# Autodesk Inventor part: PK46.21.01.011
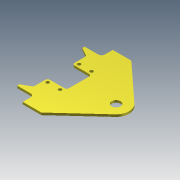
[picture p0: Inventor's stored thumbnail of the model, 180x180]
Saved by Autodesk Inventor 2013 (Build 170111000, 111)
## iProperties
Created: 2005-04
Part Number: PK46.21.01.011
Material: Steel, Mild
Document SubType Name: Modeling
Designer: salex
Manufacturer: Standard
Standards Organization: Custom
Density: 7.86 g/cm^3
Author: salex
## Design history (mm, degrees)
sketch "Эскиз1"
  geometry: L1 (77.853, 84.64)-(-265, 400); L2 (-265, 400)-(-430, 400); L3 (-430, 400)-(-430, 330); L4 (-460, 300)-(-580, 300); L5 (-500, 235)-(-500, 110); L6 (-500, 110)-(-350, 110); L7 (-330, 90)-(-330, -90); L8 (0, 0)-(-389.201, 0); L9 (77.853, -84.64)-(-265, -400); L10 (-265, -400)-(-430, -400); L11 (-500, -110)-(-350, -110); L12 (-430, -400)-(-430, -330); L13 (-460, -300)-(-580, -300); L14 (-500, -235)-(-500, -110); L15 (-580, -300)-(-580, -280); L16 (-580, -280)-(-500, -235); L17 (-580, 300)-(-580, 280); L18 (-580, 280)-(-500, 235); L19 (-500, 235)-(-500, 110); C1 r 40 at (0, 0); C2 r 15 at (-470, -140); C3 r 15 at (-360, -140); C4 r 15 at (-360, 140); C5 r 15 at (-470, 140); A1 r 115 centre (0, 0) between (77.853, -84.64) and (77.853, 84.64); A2 r 30 centre (-460, 330) between (-460, 300) and (-430, 330); A3 r 20 centre (-350, 90) between (-330, 90) and (-350, 110); A4 r 20 centre (-350, -90) between (-350, -110) and (-330, -90); A5 r 30 centre (-460, -330) between (-430, -330) and (-460, -300)
  constraints: 38 end point, 14 symmetric about line, 10 centre point, 10 point on circle, 7 perpendicular, 5 tangent, 3 equal radius, 1 coincident, 1 horizontal, 3 other
  dimensions: "d0" = 30 radius of A2; "d1" = 20 radius of A3; "d2" = 220 diameter of L6 L8; "d3" = 800 diameter of L2 L8; "d5" = 80 diameter of C1; "d6" = 330 distance from line of L7 C1.centre; "d7" = 500 distance from line of L5 C1.centre; "d9" = 100 distance between parallel lines of L2 L4; "d10" = 265 horizontal distance of L1.end C1.centre; "d11" = 115 radius of A1; "d27" = 0 vertical distance of C2.centre C3.centre; "d28" = 0 vertical distance of C4.centre C5.centre; "d29" = 0 horizontal distance of C5.centre C2.centre; "d30" = 0 horizontal distance of C3.centre C4.centre; "d31" = 280 distance of C4.centre C3.centre; "d32" = 280 diameter of C3.centre L8 (= d31); "d33" = 30 diameter of C3; "d34" = 360 horizontal distance of C3.centre C1.centre; "d35" = 110 distance of C2.centre C3.centre; "d36" = 120 distance from line of L17.end L2; "d37" = 470 diameter of L5.start L8; "d38" = 580 distance from line of C1.centre L17; "d39" = 430 distance from line of L12 C1.centre
extrude "Выдавливание1" new body sketch "Эскиз1" distance "d12" = 20; taper "d13" = 0 deg
fillet "Сопряжение1" dims "d40" = 20
body "Solid1"
